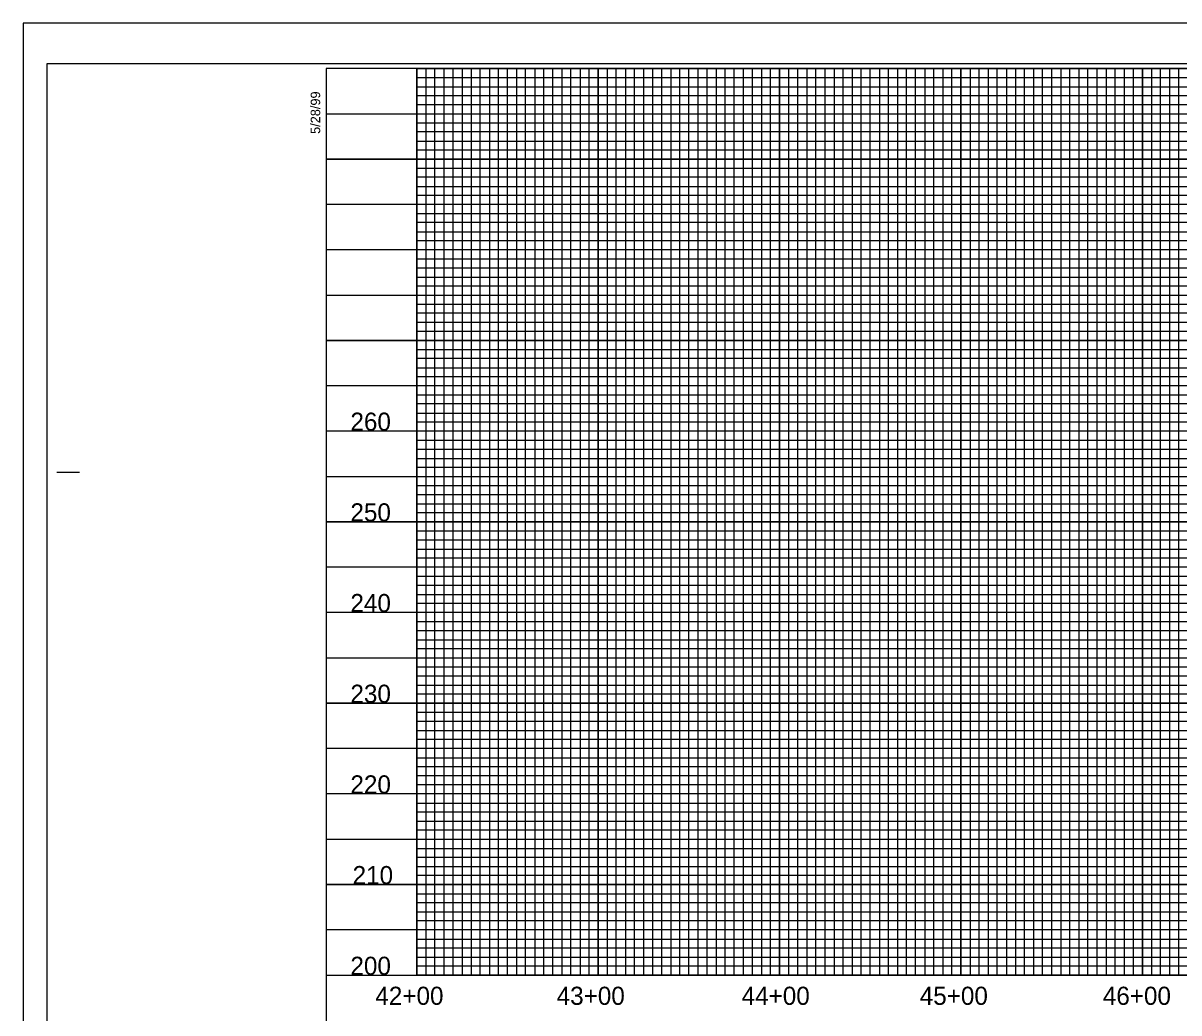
# Model space of a CAD drawing. Extents: x 1810963 to 1812908, y 722070 to 723170.
# Drawn here: x 1810963 to 1811601, y 722624 to 723170 of the extents above; entities that cross this region are included whole.
import ezdxf

# ---------------------------------------------------------------- set-up
doc = ezdxf.new("R2010")
doc.units = 0
for name, color, linetype in [('Old_Level_11', 7, 'Continuous'), ('Prop Conc 2ft 6in Curb and Gutter', 7, 'Continuous'), ('Prop RDY Traffic Signal CELL', 7, 'Continuous'), ('Prop Shade Heavy', 7, 'Continuous'), ('Prop Shade Light', 7, 'Continuous'), ('Scratch_Level_0', 7, 'Continuous'), ('Scratch_Level_3', 7, 'Continuous'), ('Scratch_Level_5', 7, 'Continuous'), ('Sheet Block Title CELL', 7, 'Continuous'), ('Sheet North Arrow CELL', 7, 'Continuous'), ('Sheet Symbology CELL', 7, 'Continuous'), ('Sheet Title CELL', 7, 'Continuous')]:
    doc.layers.add(name, color=color, linetype=linetype)

msp = doc.modelspace()

# ---------------------------------------------------------------- linework, layer by layer
at = {"layer": 'Old_Level_11'}
msp.add_lwpolyline([(1810976.46, 722092.33), (1812642.96, 722092.33), (1812642.96, 723147.43), (1810976.46, 723147.43)], close=True, dxfattribs=at)
at = {"layer": 'Prop Conc 2ft 6in Curb and Gutter'}
for p, q in [((1811180.46, 722644.88), (1811180.46, 723144.88)), ((1811230.46, 722644.88), (1811230.46, 723144.88)), ((1811280.46, 722644.88), (1811280.46, 723144.88)), ((1811330.46, 722644.88), (1811330.46, 723144.88)), ((1811380.46, 722644.88), (1811380.46, 723144.88)), ((1811430.46, 722644.88), (1811430.46, 723144.88)), ((1811480.46, 722644.88), (1811480.46, 723144.88)), ((1811530.46, 722644.88), (1811530.46, 723144.88)), ((1811580.46, 722644.88), (1811580.46, 723144.88)), ((1812230.42, 723094.88), (1811130.46, 723094.88)), ((1812430.41, 723044.88), (1811130.46, 723044.88)), ((1812430.46, 722994.88), (1811130.46, 722994.88)), ((1812630.46, 722944.88), (1811130.46, 722944.88)), ((1812630.46, 722894.88), (1811130.46, 722894.88)), ((1812630.46, 722844.88), (1811130.46, 722844.88)), ((1812630.46, 722794.88), (1811130.46, 722794.88)), ((1812630.46, 722744.88), (1811130.46, 722744.88)), ((1812630.46, 722694.88), (1811130.46, 722694.88))]:
    msp.add_line(p, q, dxfattribs=at)
at = {"layer": 'Prop RDY Traffic Signal CELL'}
for p, q in [((1812647.46, 723169.88), (1810963.46, 723169.88)), ((1810963.46, 723169.88), (1810963.46, 722069.88))]:
    msp.add_line(p, q, dxfattribs=at)
at = {"layer": 'Prop Shade Heavy'}
for points in [[(1811180.46, 723144.88), (1811180.46, 722644.88), (1811230.46, 722644.88), (1811230.46, 723144.88), (1811280.46, 723144.88), (1811280.46, 722644.88), (1811330.46, 722644.88), (1811330.46, 723144.88), (1811380.46, 723144.88), (1811380.46, 722644.88), (1811430.46, 722644.88), (1811430.46, 723144.88), (1811480.46, 723144.88), (1811480.46, 722644.88), (1811530.46, 722644.88), (1811530.46, 723144.88), (1811580.46, 723144.88), (1811580.46, 722644.88), (1811630.46, 722644.88)], [(1811130.46, 723094.88), (1812230.42, 723094.88)], [(1812430.46, 723044.88), (1811130.46, 723044.88), (1811130.46, 722994.88), (1812430.46, 722994.88)], [(1812630.46, 722944.88), (1811130.46, 722944.88), (1811130.46, 722894.88), (1812630.46, 722894.88)], [(1812630.46, 722844.88), (1811130.46, 722844.88), (1811130.46, 722794.88), (1812630.46, 722794.88)], [(1812630.46, 722744.88), (1811130.46, 722744.88), (1811130.46, 722744.88), (1811130.46, 722694.88), (1812630.46, 722694.88)]]:
    msp.add_lwpolyline(points, dxfattribs=at)
at = {"layer": 'Prop Shade Light'}
for p, q in [((1811205.46, 723144.88), (1811205.46, 722644.88)), ((1811255.46, 722644.88), (1811255.46, 723144.88)), ((1811255.46, 723144.88), (1811305.46, 723144.88)), ((1811305.46, 723144.88), (1811305.46, 722644.88)), ((1811355.46, 722644.88), (1811355.46, 723144.88)), ((1811355.46, 723144.88), (1811405.46, 723144.88)), ((1811405.46, 723144.88), (1811405.46, 722644.88)), ((1811455.46, 722644.88), (1811455.46, 723144.88)), ((1811455.46, 723144.88), (1811505.46, 723144.88)), ((1811505.46, 723144.88), (1811505.46, 722644.88)), ((1811555.46, 722644.88), (1811555.46, 723144.88)), ((1811555.46, 723144.88), (1811605.46, 723144.88)), ((1811130.46, 723119.88), (1812230.42, 723119.88)), ((1811205.46, 722644.88), (1811255.46, 722644.88)), ((1811305.46, 722644.88), (1811355.46, 722644.88)), ((1811405.46, 722644.88), (1811455.46, 722644.88)), ((1811505.46, 722644.88), (1811555.46, 722644.88))]:
    msp.add_line(p, q, dxfattribs=at)
for points in [[(1812430.46, 723069.88), (1811130.46, 723069.88), (1811130.46, 723019.88), (1812430.46, 723019.88)], [(1812630.46, 722969.88), (1811130.46, 722969.88), (1811130.46, 722919.88), (1812455.46, 722919.88)], [(1812630.46, 722869.88), (1811130.46, 722869.88), (1811130.46, 722819.88), (1812630.46, 722819.88)], [(1812630.46, 722769.88), (1811130.46, 722769.88), (1811130.46, 722719.88), (1812630.46, 722719.88)], [(1812630.46, 722669.88), (1811130.46, 722669.88)]]:
    msp.add_lwpolyline(points, dxfattribs=at)
at = {"layer": 'Scratch_Level_3'}
msp.add_lwpolyline([(1811180.46, 723144.88), (1812230.46, 723144.88), (1812230.46, 723092.45), (1812430.5, 723092.45), (1812430.41, 722983.83), (1812580.46, 722983.83), (1812580.46, 722644.88), (1811180.46, 722644.88)], close=True, dxfattribs=at)
at = {"layer": 'Scratch_Level_5'}
msp.add_lwpolyline([(1811180.46, 722983.83), (1811180.46, 722644.88), (1812580.46, 722644.88), (1812580.46, 722983.83)], dxfattribs=at)
at = {"layer": 'Sheet North Arrow CELL'}
msp.add_lwpolyline([(1810963.46, 722069.88), (1812647.46, 722069.88), (1812647.46, 723169.88), (1810963.46, 723169.88)], close=True, dxfattribs=at)
at = {"layer": 'Sheet Symbology CELL'}
for p, q in [((1810981.96, 722922.38), (1810994.46, 722922.38)), ((1811130.46, 722644.88), (1812630.46, 722644.88))]:
    msp.add_line(p, q, dxfattribs=at)
msp.add_lwpolyline([(1812630.46, 723144.88), (1811130.46, 723144.88), (1811130.46, 722094.88), (1812630.46, 722094.88)], close=True, dxfattribs=at)
at = {"layer": 'Sheet Title CELL'}
for p, q in [((1811180.46, 723139.88), (1812230.42, 723139.88)), ((1811180.46, 723134.88), (1811180.46, 723134.88)), ((1812230.42, 723134.82), (1811180.46, 723134.53)), ((1811180.46, 723129.88), (1812230.42, 723129.88)), ((1812230.42, 723099.88), (1811180.46, 723099.88)), ((1811180.46, 723099.88), (1811180.46, 723089.88)), ((1811180.46, 723089.88), (1812430.46, 723089.88)), ((1812430.41, 723009.88), (1811180.46, 723009.88)), ((1812430.46, 723004.88), (1811180.46, 723004.88)), ((1812430.46, 722999.88), (1811180.46, 722999.88)), ((1811180.46, 722989.88), (1812430.46, 722989.88)), ((1812430.46, 722984.88), (1811180.46, 722984.88)), ((1811180.46, 722979.88), (1812580.46, 722979.88)), ((1812580.46, 722959.88), (1811180.46, 722959.88)), ((1811180.46, 722954.88), (1812580.46, 722954.88)), ((1812580.46, 722934.88), (1811180.46, 722934.88)), ((1811180.46, 722929.88), (1812580.46, 722929.88)), ((1812580.46, 722909.88), (1811180.46, 722909.88)), ((1811180.46, 722904.88), (1812580.46, 722904.88)), ((1812580.46, 722899.88), (1811180.46, 722899.88)), ((1811180.46, 722889.88), (1812580.46, 722889.88)), ((1812580.46, 722884.88), (1811180.46, 722884.88)), ((1811180.46, 722879.88), (1812580.46, 722879.88)), ((1812580.46, 722874.88), (1811180.46, 722874.88)), ((1811180.46, 722864.88), (1812580.46, 722864.88)), ((1812580.46, 722859.88), (1811180.46, 722859.88)), ((1811180.46, 722854.88), (1812580.46, 722854.88)), ((1812580.46, 722849.88), (1811180.46, 722849.88)), ((1811180.46, 722839.88), (1812580.46, 722839.88)), ((1812580.46, 722834.88), (1811180.46, 722834.88)), ((1811180.46, 722829.88), (1812580.46, 722829.88)), ((1812580.46, 722824.88), (1811180.46, 722824.88)), ((1811180.46, 722814.88), (1812580.46, 722814.88)), ((1812580.46, 722809.88), (1811180.46, 722809.88)), ((1811180.46, 722804.88), (1812580.46, 722804.88)), ((1812580.46, 722799.88), (1811180.46, 722799.88)), ((1811180.46, 722789.88), (1812580.46, 722789.88)), ((1812580.46, 722784.88), (1811180.46, 722784.88)), ((1811180.46, 722779.88), (1812580.46, 722779.88)), ((1812580.46, 722774.88), (1811180.46, 722774.88)), ((1811180.46, 722764.88), (1812580.46, 722764.88)), ((1812580.46, 722759.88), (1811180.46, 722759.88)), ((1812580.46, 722754.88), (1811180.46, 722754.88)), ((1812580.46, 722749.88), (1811180.46, 722749.88)), ((1811180.46, 722739.88), (1812580.46, 722739.88)), ((1812580.46, 722734.88), (1811180.46, 722734.88)), ((1811180.46, 722729.88), (1812580.46, 722729.88)), ((1812580.46, 722724.88), (1811180.46, 722724.88)), ((1811180.46, 722714.88), (1812580.46, 722714.88)), ((1812580.46, 722709.88), (1811180.46, 722709.88)), ((1811180.46, 722704.88), (1812580.46, 722704.88)), ((1812580.46, 722699.88), (1811180.46, 722699.88)), ((1811180.46, 722689.88), (1812580.46, 722689.88)), ((1812580.46, 722684.88), (1811180.46, 722684.88)), ((1811180.46, 722679.88), (1812580.46, 722679.88)), ((1812580.46, 722674.88), (1811180.46, 722674.88)), ((1811180.46, 722664.88), (1812580.46, 722664.88)), ((1812580.46, 722659.88), (1811180.46, 722659.88)), ((1811180.46, 722654.88), (1812580.46, 722654.88))]:
    msp.add_line(p, q, dxfattribs=at)
for points in [[(1811185.46, 723144.88), (1811185.46, 722644.88), (1811190.46, 722644.88), (1811190.46, 723144.88), (1811195.46, 723144.88), (1811195.46, 722644.88), (1811200.46, 722644.88), (1811200.46, 723144.88), (1811210.46, 723144.88), (1811210.46, 722644.88), (1811215.46, 722644.88), (1811215.46, 723144.88), (1811220.46, 723144.88), (1811220.46, 722644.88), (1811225.46, 722644.88), (1811235.46, 722644.88), (1811240.46, 722644.88), (1811240.46, 723144.88), (1811245.46, 723144.88), (1811245.46, 722644.88), (1811250.46, 722644.88), (1811250.46, 723144.88), (1811260.46, 723144.88), (1811260.46, 722644.88), (1811265.46, 722644.88), (1811265.46, 723144.88), (1811270.46, 723144.88), (1811270.46, 722644.88), (1811275.46, 722644.88), (1811275.46, 723144.88), (1811285.46, 723144.88), (1811285.46, 722644.88), (1811290.46, 722644.88), (1811290.46, 723144.88), (1811295.46, 723144.88), (1811295.46, 722644.88), (1811300.46, 722644.88), (1811300.46, 723144.88), (1811310.46, 723144.88), (1811310.46, 722644.88), (1811315.46, 722644.88), (1811315.46, 723144.88), (1811320.46, 723144.88), (1811320.46, 722644.88), (1811325.46, 722644.88), (1811325.46, 723144.88), (1811335.46, 723144.88), (1811335.46, 722644.88), (1811340.46, 722644.88), (1811340.46, 723144.88), (1811345.46, 723144.88), (1811345.46, 722644.88), (1811350.46, 722644.88), (1811350.46, 723144.88), (1811360.46, 723144.88), (1811360.46, 722644.88), (1811365.46, 722644.88), (1811365.46, 723144.88), (1811370.46, 723144.88), (1811370.46, 722644.88), (1811375.46, 722644.88), (1811375.46, 723144.88), (1811385.46, 723144.88), (1811385.46, 722644.88), (1811390.46, 722644.88), (1811390.46, 723144.88), (1811395.46, 723144.88), (1811395.46, 722644.88)], [(1811225.46, 722644.88), (1811225.46, 723144.88), (1811235.46, 723144.88), (1811235.46, 722644.88)], [(1811395.46, 722644.88), (1811400.46, 722644.88), (1811400.46, 723144.88), (1811410.46, 723144.88), (1811410.46, 722644.88), (1811415.46, 722644.88), (1811415.46, 723144.88), (1811420.46, 723144.88), (1811420.46, 722644.88), (1811425.46, 722644.88), (1811425.46, 723144.88), (1811435.46, 723144.88), (1811435.46, 722644.88), (1811440.46, 722644.88), (1811440.46, 723144.88), (1811445.46, 723144.88), (1811445.46, 722644.88), (1811450.46, 722644.88), (1811450.46, 723144.88), (1811460.46, 723144.88), (1811460.46, 722644.88), (1811465.46, 722644.88), (1811465.46, 723144.88), (1811470.46, 723144.88), (1811470.46, 722644.88), (1811475.46, 722644.88), (1811475.46, 723144.88), (1811485.46, 723144.88), (1811485.46, 722644.88), (1811490.46, 722644.88), (1811490.46, 723144.88), (1811495.46, 723144.88), (1811495.46, 722644.88), (1811500.46, 722644.88), (1811500.46, 723144.88), (1811510.46, 723144.88), (1811510.46, 722644.88), (1811515.46, 722644.88), (1811515.46, 723144.88), (1811520.46, 723144.88), (1811520.46, 722644.88), (1811525.46, 722644.88), (1811525.46, 723144.88), (1811535.46, 723144.88), (1811535.46, 722644.88), (1811540.46, 722644.88), (1811540.46, 723144.88), (1811545.46, 723144.88), (1811545.46, 722644.88), (1811550.46, 722644.88), (1811550.46, 723144.88), (1811560.46, 723144.88), (1811560.46, 722644.88), (1811565.46, 722644.88), (1811565.46, 723144.88), (1811570.46, 723144.88), (1811570.46, 722644.88), (1811575.46, 722644.88), (1811575.46, 723144.88), (1811585.46, 723144.88), (1811585.46, 722644.88), (1811590.46, 722644.88), (1811590.46, 723144.88), (1811595.46, 723144.88), (1811595.46, 722644.88), (1811600.46, 722644.88), (1811600.46, 723144.88), (1811610.46, 723144.88)], [(1812230.42, 723124.88), (1811180.46, 723124.88), (1811180.46, 723114.88), (1812230.42, 723114.88)], [(1812230.42, 723109.88), (1811180.46, 723109.88), (1811180.46, 723104.88), (1812230.42, 723104.88)], [(1812430.46, 723084.88), (1811180.46, 723084.88), (1811180.46, 723079.88), (1812430.46, 723079.88)], [(1812430.46, 723074.88), (1811180.46, 723074.88), (1811180.46, 723064.88), (1812430.46, 723064.88)], [(1812430.46, 723059.88), (1811180.46, 723059.88), (1811180.46, 723054.88), (1812430.46, 723054.88)], [(1812430.46, 723049.88), (1811180.46, 723049.88), (1811180.46, 723039.88), (1812430.46, 723039.88)], [(1812430.46, 723034.78), (1811180.56, 723034.78), (1811180.56, 723029.88), (1812430.46, 723029.88)], [(1812430.46, 723024.88), (1811180.46, 723024.88), (1811180.46, 723014.88), (1812430.46, 723014.88)], [(1812580.46, 722974.88), (1811180.46, 722974.88), (1811180.46, 722964.88), (1812580.46, 722964.88)], [(1812580.46, 722949.88), (1811180.46, 722949.88), (1811180.46, 722939.88), (1812580.46, 722939.88)], [(1812580.46, 722924.88), (1811180.46, 722924.88), (1811180.46, 722914.88), (1812580.46, 722914.88)], [(1812580.46, 722649.88), (1811180.46, 722649.88)]]:
    msp.add_lwpolyline(points, dxfattribs=at)

# ---------------------------------------------------------------- texts
at = {"layer": 'Scratch_Level_0'}
for s, p in [('260', (1811143.89, 722945.13)), ('250', (1811143.89, 722895.13)), ('240', (1811143.89, 722845.13)), ('230', (1811143.89, 722795.13)), ('220', (1811143.89, 722745.13)), ('210', (1811145.09, 722695.13)), ('200', (1811143.89, 722645.13))]:
    msp.add_text(s, height=10, dxfattribs=at).set_placement(p)
at = {"layer": 'Sheet Block Title CELL'}
for s, p in [('42+00', (1811157.64, 722628.6)), ('43+00', (1811257.58, 722628.6)), ('44+00', (1811359.54, 722628.6)), ('45+00', (1811457.72, 722628.6)), ('46+00', (1811558.64, 722628.6))]:
    msp.add_text(s, height=10, dxfattribs=at).set_placement(p)
at = {"layer": 'Sheet Symbology CELL'}
msp.add_text('5/28/99', height=5.25, rotation=90, dxfattribs=at).set_placement((1811127.22, 723108.79))

doc.saveas('drawing.dxf')
